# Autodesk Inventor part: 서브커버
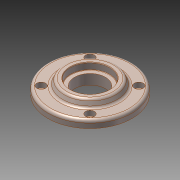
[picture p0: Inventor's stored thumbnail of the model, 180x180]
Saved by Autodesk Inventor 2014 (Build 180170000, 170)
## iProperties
Created: 2013-01
Part Number: 서브커버
Document SubType Name: Modeling
Designer: 한국산업디자인학원[gmhk.co.kr]
Density: 7.25 g/cm^3
Material: 주철
Mass: 431.687 g
Surface Area: 179.079 cm^2
Volume: 59.543 cm^3
Appearance: 강철(1)
Author: 한국산업디자인학원[gmhk.co.kr]
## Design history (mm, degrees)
sketch "스케치2"
  geometry: L1 (-45, 0)-(0, 0); L2 (-25.784, -7)-(25.784, -7) reference; L3 (0, -7)-(0, 15); L4 (-31, -23)-(-31, 0) reference; L5 (-26.5, -7)-(-26.5, -3); L6 (-26.5, -3)-(0, -3); L7 (-26.5, -7)-(-31, -7); L8 (-31, 0)-(-45, 0); L9 (-45, 0)-(-45, 8); L10 (-45, 8)-(-30, 8); L11 (-30, 8)-(-26.736, 15); L12 (-26.736, 15)-(0, 15)
  constraints: 25 end point, 6 perpendicular, 3 point on line, 1 collinear, 1 horizontal, 1 midpoint, 1 parallel, 1 vertical, 3 other
  dimensions: "d0" = 53 diameter of L5 L3; "d1" = 4 distance between parallel lines of L6 L2; "d2" = 8 distance between parallel lines of L10 L1; "d3" = 7 distance between parallel lines of L12 L10; "d4" = 60 diameter of L10.end L3; "d5" = 115 deg angle of L11 L10; "d27" = 90 diameter of L9 L3
revolve "회전1" sketch "스케치2" stored, may be unused: angle "d6" = 90 deg
hole "구멍1" diameter "d9" = 33; stored, may be unused: countersink angle "d13" = 90 deg, drill point angle "d15" = 118 deg; dims "d10" = 6, "d11" = 42, "d12" = 7.3, "d14" = 8, "d38" = 10, "d39" = 10
fillet "모깎기1" dims "d16" = 3
chamfer "모따기1" distance "d17" = 0.7; stored, may be unused: second distance "d18" = 2, angle "d19" = 30 deg
sketch "스케치3"
  geometry: C1 r 2.067 at (26.163, 26.163) reference; 1 further point
hole "구멍2" sketch "스케치3" at (26.163, 26.163) diameter "d20" = 5.4; stored, may be unused: countersink angle "d24" = 90 deg, drill point angle "d26" = 118 deg; dims "d21" = 6, "d22" = 9.5, "d23" = 5.5, "d25" = 8
fillet "모깎기2" dims "d31" = 0.3
fillet "모깎기3" dims "d32" = 3
chamfer "모따기2" distance "d35" = 1; stored, may be unused: second distance "d36" = 2, angle "d37" = 45 deg
node "솔리드1"
pattern_circular "원형 패턴1" dims angle "d29" = 360 deg
node "참조3"
